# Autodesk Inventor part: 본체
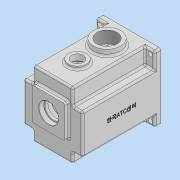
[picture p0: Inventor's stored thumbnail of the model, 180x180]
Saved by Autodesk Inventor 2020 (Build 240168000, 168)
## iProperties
Created: 2022-01
Part Number: 본체
Material: 일반
Document SubType Name: Modeling
Designer: user
Density: 1 g/cm^3
Appearance: 기본값
Author: user
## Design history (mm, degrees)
sketch "스케치1"
  geometry: L1 (49, 55)-(-49, 55); L2 (-49, 55)-(-49, -55); L3 (-49, -55)-(49, -55); L4 (49, -55)-(49, 55); L5 (49, 55)-(-49, -55); L6 (-49, 55)-(49, -55); 1 further point
  constraints: 12 end point, 2 midpoint, 2 parallel, 1 horizontal, 1 perpendicular
  dimensions: "d0" = 98 distance of L3.end L2.end; "d1" = 110 distance of L2.end L1.end
extrude "돌출1" new body sketch "스케치1" distance "d2" = 130; taper "d3" = 0 deg
sketch "스케치3"
  geometry: L1 (49, 55)-(-49, 55) reference; L2 (49, 55)-(33, 55); L3 (33, 55)-(33, 28); L4 (49, -55)-(49, 55) reference; L5 (49, 55)-(49, 28); L6 (33, 28)-(49, 28); 1 further point
  constraints: 8 end point, 2 point on line, 1 horizontal, 1 vertical
  dimensions: "d8" = 16 distance of L1.start L2.end; "d9" = 27 distance of L2.end L3.end
extrude "돌출3" cut sketch "스케치3" distance "d10" = 120; taper "d11" = 0 deg
sketch "스케치4"
  geometry: L1 (-49, 55)-(-49, -55) reference; L2 (-49, -55)-(-33, -55); L3 (-33, -55)-(-33, -38); L4 (-33, -38)-(-49, -38); L5 (-49, -38)-(-49, -55); 2 further points
  constraints: 8 end point, 2 parallel, 1 horizontal, 1 perpendicular
  dimensions: "d12" = 16 distance of L4.end L3.end; "d13" = 17 distance of L3.end L2.end
extrude "돌출4" cut sketch "스케치4" distance "d14" = 120; taper "d15" = 0 deg
sketch "스케치5"
  geometry: L1 (49, 0)-(49, -89); C1 r 15 at (49, -89)
  constraints: 2 end point, 1 centre point, 1 coincident, 1 vertical
  dimensions: "d16" = 89 distance of L1.start L1.end; "d17" = 30 diameter of C1
extrude "돌출5" join sketch "스케치5" distance "d18" = 5; taper "d19" = 0 deg
sketch "스케치6"
  geometry: L1 (49, 0)-(49, -40); C1 r 22.5 at (49, -40)
  constraints: 2 end point, 1 centre point, 1 coincident, 1 vertical
  dimensions: "d20" = 40 distance of L1.start L1.end; "d21" = 45 diameter of C1
extrude "돌출6" join sketch "스케치6" distance "d22" = 10; taper "d23" = 0 deg
sketch "스케치8"
  geometry: L1 (27, -21)-(-27, -21); L2 (-27, -21)-(-27, 33); L3 (-27, 33)-(27, 33); L4 (27, 33)-(27, -21); L5 (27, -21)-(-27, 33); L6 (-27, -21)-(27, 33); L7 (-33, -55)-(33, -55) reference; 2 further points
  constraints: 12 end point, 2 parallel, 1 horizontal, 1 midpoint, 1 perpendicular, 1 vertical alignment
  dimensions: "d25" = 54 distance of L2.end L3.end; "d26" = 54 distance of L1.end L2.end; "d191" = 61 distance from line of point (0, 6) L7
extrude "돌출7" join sketch "스케치8" distance "d27" = 7; taper "d28" = 0 deg
sketch "스케치9"
  geometry: L1 (-49, 55)-(49, 55) reference; L2 (-49, 55)-(-42, 55); L3 (-42, 55)-(-49, 55); L4 (-42, 55)-(-42, 48); L5 (-49, -55)-(-49, 55) reference; L6 (-49, -55)-(-42, -55); L7 (49, -55)-(-49, -55) reference; L8 (-42, -55)-(-42, -48); L9 (49, 55)-(49, -55) reference; L10 (49, -55)-(42, -55); L11 (42, -55)-(42, -48); L12 (49, 55)-(33, 55) reference; L13 (49, 55)-(42, 55); L14 (42, 55)-(42, 48); 5 further points
  constraints: 18 end point, 4 coincident, 4 point on line, 3 perpendicular, 1 collinear, 1 vertical
  dimensions: "d29" = 7 distance of L1.start L2.end; "d30" = 7 distance of L2.end L1.start (derived); "d31" = 7 distance of L2.end L4.end; "d32" = 7 distance of L5.start L6.end; "d33" = 7 distance of L6.end L8.end; "d34" = 7 distance of L7.start L10.end; "d35" = 7 distance of L10.end L11.end; "d36" = 7 distance of L1.end L13.end; "d37" = 7 distance of L13.end L14.end
hole "구멍1" sketch "스케치9" at (-42, 48), (-42, -48), (42, -48), (42, 48) diameter "d38" = 7; stored, may be unused: countersink angle "d42" = 90 deg, drill point angle "d44" = 118 deg; dims "d39" = 10, "d40" = 4, "d41" = 2, "d43" = 14.2
sketch "스케치10"
  geometry: L1 (-23, 50)-(-8.143, 50); L2 (23, 50)-(37.857, 50); L3 (49, -55)-(-49, -55) reference; L4 (0, -55)-(50, -55); L5 (0, 48)-(-26, 48); L6 (0, 48)-(26, 48); L7 (-26, 48)-(-26, 31.729); L8 (-26, 48)-(-9.729, 48); L9 (26, 48)-(26, 31.729); L10 (26, 48)-(42.271, 48); A1 r 45 centre (0, -5) between (-26, 31.729) and (26, 31.729)
  constraints: 18 end point, 6 horizontal, 2 perpendicular, 2 point on circle, 1 centre point, 1 midpoint, 1 parallel
  dimensions: "d57" = 90 diameter of A1; "d59" = 26 distance of L5.start L5.end; "d60" = 26 distance of L5.start L6.end; "d61" = 90 deg angle of L7 L8; "d62" = 90 deg angle of L9 L10
extrude "돌출8" cut sketch "스케치10" distance "d63" = 9; taper "d64" = 0 deg
sketch "스케치16"
  geometry: L1 (-130, 83)-(-130, 110) reference; L2 (-10, 83)-(-130, 83) reference; 2 further points
  constraints: 1 other
  dimensions: "d81" = 65 distance from line of L1 point (-65, 50); "d82" = 33 distance from line of point (-65, 50) L2
feature "엠보싱1" sketch "스케치16" dims "d83" = 0.5, "d84" = 0
sketch "스케치17"
  geometry: C1 r 22.5 at (0, 0) reference; 2 further points
  constraints: 1 coincident
hole "구멍2" sketch "스케치17" at (0, 0) diameter "d86" = 33.376; stored, may be unused: countersink angle "d90" = 90 deg, drill point angle "d92" = 118 deg; dims "d87" = 43, "d88" = 4, "d89" = 2, "d91" = 50
sketch "스케치18"
  geometry: C1 r 15 at (0, 0) reference; C2 r 10 at (0, 0); 1 further point
  constraints: 1 centre point, 1 coincident
  dimensions: "d93" = 20 diameter of C2
extrude "돌출14" cut sketch "스케치18" distance "d97" = 26; taper "d98" = 0 deg
fillet "모깎기6" dims "d154" = 3
fillet "모깎기7" dims "d155" = 3
fillet "모깎기8" dims "d156" = 3
fillet "모깎기9" dims "d157" = 3
fillet "모깎기10" dims "d158" = 3
fillet "모깎기11" dims "d159" = 3
fillet "모깎기12" dims "d160" = 3
sketch "스케치36"
  geometry: L1 (-26, 48)-(26, 48) reference; L2 (-26, 31.729)-(-26, 48) reference; L3 (26, 48)-(26, 31.729) reference; L4 (23, 45)-(-23, 45); L5 (-23, 45)-(-23, 30.143); L6 (23, 30.143)-(23, 45); A1 r 45 centre (0, -5) between (-26, 31.729) and (26, 31.729) reference; A2 r 42 centre (0, -5) between (-23, 30.143) and (23, 30.143); 1 further point
  constraints: 6 end point, 2 point on circle, 1 centre point, 3 other
  dimensions: "d161" = 3 distance between parallel lines of L1 L4
extrude "돌출27" cut sketch "스케치36" distance "d162" = 112; taper "d163" = 0 deg
sketch "스케치37"
  geometry: C1 r 21 at (0, 6); C2 r 15 at (0, -25); A1 r 42 centre (0, -5) between (-23, 30.143) and (23, 30.143) reference; 2 further points
  constraints: 2 centre point, 2 vertical alignment
  dimensions: "d166" = 20 distance of C2.centre A1.centre; "d167" = 11 distance of C1.centre A1.centre; "d168" = 42 diameter of C1; "d169" = 30 diameter of C2
extrude "돌출28" join sketch "스케치37" distance "d170" = 7; taper "d171" = 0 deg
sketch "스케치38"
  geometry: A1 r 21 centre (0, 6) between (8.978, -12.984) and (-8.978, -12.984) reference; 2 further points
  constraints: 1 coincident
hole "구멍4" sketch "스케치38" at (0, 6) diameter "d172" = 28; stored, may be unused: countersink angle "d176" = 90 deg, drill point angle "d178" = 118 deg; dims "d173" = 7, "d174" = 35, "d175" = 10, "d177" = 9
sketch "스케치39"
  geometry: A1 r 15 centre (0, -25) between (-8.978, -12.984) and (8.978, -12.984) reference; 2 further points
  constraints: 1 coincident
hole "구멍5" sketch "스케치39" at (0, -25) diameter "d179" = 19; stored, may be unused: countersink angle "d183" = 90 deg, drill point angle "d185" = 0 deg; dims "d180" = 7, "d181" = 22, "d182" = 7, "d184" = 10
fillet "모깎기13" dims "d186" = 3
fillet "모깎기14" dims "d187" = 0.3
chamfer "모따기2" distance "d188" = 1; stored, may be unused: second distance "d189" = 2, angle "d190" = 45 deg
sketch "스케치40"
  geometry: C1 r 14 at (0, 6) reference; C2 r 16 at (0, 6); 1 further point
  constraints: 1 centre point, 1 coincident
  dimensions: "d192" = 32 diameter of C2
extrude "돌출29" cut sketch "스케치40" distance "d193" = 8.3; taper "d194" = 0 deg
sketch "스케치41"
  geometry: L1 (-36, -1)-(-41.809, -1); L2 (-36, -9)-(-41.809, -9); A1 r 42 centre (0, -5) between (-23, 30.143) and (23, 30.143) reference; A2 r 4 centre (-36, -5) between (-36, -1) and (-36, -9); A3 r 42 centre (0, -5) between (-23, 30.143) and (23, 30.143) reference; 2 further points
  constraints: 4 end point, 4 point on circle, 2 horizontal, 2 tangent, 1 centre point, 1 horizontal alignment
  dimensions: "d195" = 8 diameter of A2; "d196" = 36 distance of A1.centre A2.centre
extrude "돌출30" join sketch "스케치41" stored distance "d197" = 8.3; taper "d198" = 0 deg
sketch "스케치42"
  geometry: A1 r 4 centre (-36, -5) between (-36, -9) and (-36, -1) reference; A2 r 4 centre (36, -5) between (36, -1) and (36, -9) reference; 1 further point
hole "구멍6" sketch "스케치42" at (-36, -5), (36, -5) diameter "d199" = 3.242; stored, may be unused: countersink angle "d203" = 90 deg, drill point angle "d205" = 118 deg; dims "d200" = 7, "d201" = 22, "d202" = 7, "d204" = 9
fillet "모깎기15" dims "d206" = 6
fillet "모깎기16" dims "d207" = 3
fillet "모깎기17" dims "d208" = 3
fillet "모깎기18" dims "d209" = 3
fillet "모깎기19" dims "d210" = 3
chamfer "모따기3" distance "d211" = 1; stored, may be unused: second distance "d212" = 2, angle "d213" = 45 deg
fillet "모깎기20" dims "d214" = 3
fillet "모깎기21" dims "d215" = 3
sketch "스케치43"
  geometry: C1 r 10 at (20, 80) reference; 2 further points
  constraints: 1 coincident
hole "구멍7" sketch "스케치43" at (20, 80) diameter "d216" = 30; stored, may be unused: countersink angle "d220" = 90 deg, drill point angle "d222" = 0 deg; dims "d217" = 7, "d218" = 22, "d219" = 7, "d221" = 5
chamfer "모따기4" distance "d223" = 1; stored, may be unused: second distance "d224" = 2, angle "d225" = 45 deg
fillet "모깎기22" dims "d226" = 0.3
chamfer "모따기5" distance "d227" = 0.8; stored, may be unused: second distance "d228" = 2, angle "d229" = 30 deg
node "솔리드1" dims "d195" = 8, "d196" = 36
mirror "미러1"
mirror "미러2"
mirror "미러3"
feature "A9D066F2-1C7D-4E18-AEED-F7BC21143FA4" dims "d38" = 7, "d39" = 10, "d40" = 4, "d41" = 2, "d42" = 90 deg, "d43" = 14.2, "d44" = 118 deg
